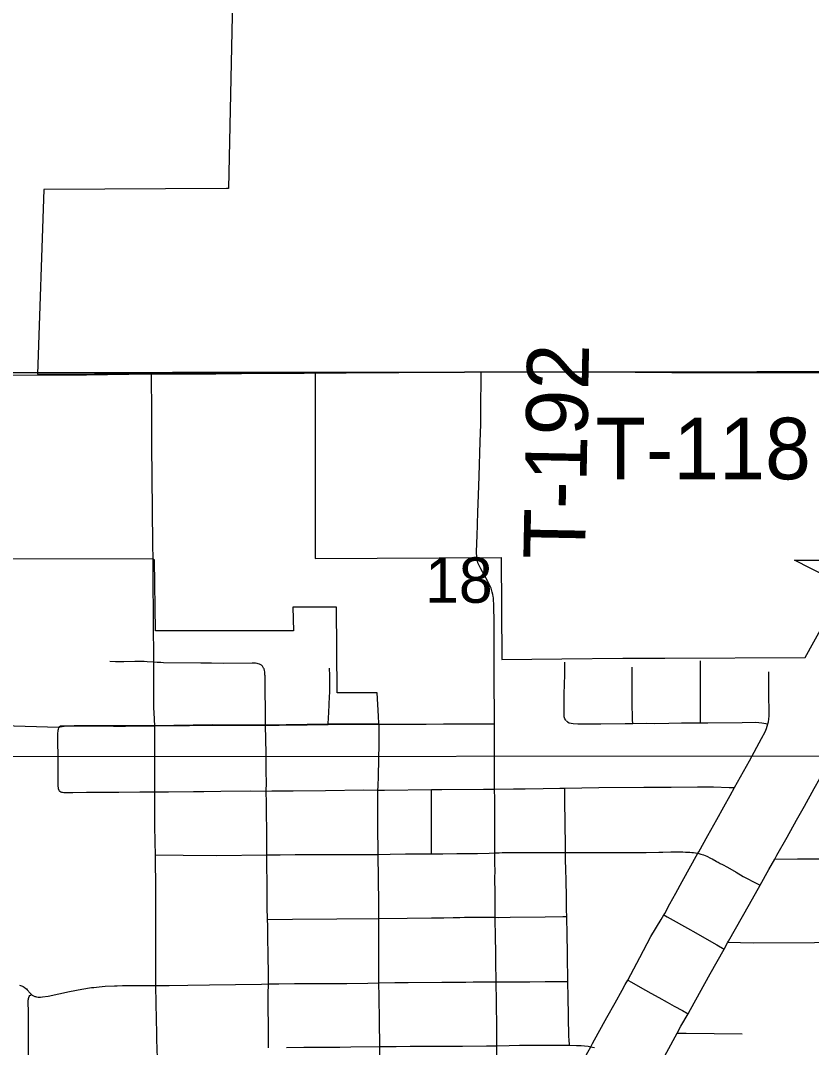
# Model space of a CAD drawing. Extents: x 0 to 34, y 0 to 22.
# Drawn here: x 3.7866 to 4.151, y 16.4424 to 16.9158 of the extents above; entities that cross this region are included whole.
import ezdxf

# ---------------------------------------------------------------- set-up
doc = ezdxf.new("R2010")
doc.units = 0
for name, color, linetype in [('GM_X_City_Street', 7, 'Continuous'), ('GM_X_Corporation', 7, 'Continuous'), ('GM_X_Section_Text', 7, 'Continuous'), ('GM_X_State_Route', 7, 'Continuous'), ('GM_X_Township_Road', 7, 'Continuous'), ('GM_X_Township_Road_Text', 7, 'Continuous')]:
    doc.layers.add(name, color=color, linetype=linetype)

msp = doc.modelspace()

# ---------------------------------------------------------------- linework, layer by layer
at = {"layer": 'GM_X_City_Street'}
for points in [[(4.038, 16.59303), (4.03779, 16.59328), (4.03744, 16.59383), (4.03724, 16.59435), (4.03712, 16.59485), (4.037, 16.59702), (4.03703, 16.60158), (4.03706, 16.60497), (4.03729, 16.61021), (4.03736, 16.61391), (4.03732, 16.61766), (4.03733, 16.61969), (4.03738, 16.62)], [(4.06864, 16.5918), (4.06861, 16.59346), (4.06848, 16.60165), (4.06848, 16.60596), (4.06846, 16.6081), (4.06846, 16.61364), (4.06843, 16.61585), (4.06841, 16.61775)], [(4.09996, 16.59198), (4.09994, 16.59339), (4.09987, 16.60153), (4.0999, 16.6157), (4.09982, 16.6206)], [(4.131, 16.59151), (4.13122, 16.59242), (4.13139, 16.59365), (4.13152, 16.59527), (4.13151, 16.59774), (4.13145, 16.60411), (4.13142, 16.61554)], [(3.80413, 16.56138), (3.80405, 16.56173), (3.80401, 16.56206), (3.80395, 16.5629), (3.80392, 16.56434), (3.80385, 16.56839), (3.80384, 16.57492), (3.80372, 16.58496), (3.80374, 16.58602), (3.80381, 16.58732), (3.8039, 16.58822), (3.80397, 16.58863), (3.80408, 16.58912), (3.80429, 16.58971)], [(3.80429, 16.58971), (3.80448, 16.58998), (3.80482, 16.59023), (3.80518, 16.59036), (3.80574, 16.59042), (3.80665, 16.59045), (3.81165, 16.5906), (3.82935, 16.59055), (3.83489, 16.59056), (3.84838, 16.59061), (3.8645, 16.59086), (3.87047, 16.59089), (3.87699, 16.59095), (3.89949, 16.59091), (3.90568, 16.59102), (3.90932, 16.59107), (3.91498, 16.59109), (3.91684, 16.5911), (3.91862, 16.59114), (3.92601, 16.59127), (3.9283, 16.5913), (3.93422, 16.59135), (3.9384, 16.59138), (3.94584, 16.59137), (3.94899, 16.59137), (3.95182, 16.59139), (3.95723, 16.59139), (3.96438, 16.59145), (3.97341, 16.59146), (3.9815, 16.59151), (3.98493, 16.59153), (3.98773, 16.59153), (3.99147, 16.59155), (3.99521, 16.59155), (3.99708, 16.59158), (3.99922, 16.59155), (4.00495, 16.59158)], [(3.85036, 16.38215), (3.85037, 16.39177), (3.85033, 16.39701), (3.85026, 16.40096), (3.8501, 16.40624), (3.84999, 16.41042), (3.84998, 16.41159), (3.84991, 16.41969), (3.84978, 16.43021), (3.84963, 16.43738), (3.84954, 16.44175), (3.84944, 16.44609), (3.8494, 16.44915), (3.84926, 16.45534), (3.84885, 16.47057), (3.84885, 16.4709), (3.84895, 16.48456), (3.84891, 16.49966), (3.84886, 16.51438), (3.84876, 16.53116), (3.84863, 16.53697), (3.84846, 16.54471), (3.84841, 16.56016), (3.84838, 16.59061)], [(3.90079, 16.44214), (3.90078, 16.45019), (3.90069, 16.46295), (3.90068, 16.46699), (3.90076, 16.47165), (3.90084, 16.47629), (3.90065, 16.48478), (3.90047, 16.49331), (3.90045, 16.49848), (3.90039, 16.50144), (3.90028, 16.50704), (3.90016, 16.51832), (3.90006, 16.52628), (3.90006, 16.53114), (3.90001, 16.5342), (3.89999, 16.53692), (3.89999, 16.53995), (3.9, 16.54297), (3.89997, 16.54979), (3.89991, 16.55504), (3.89983, 16.56059), (3.89985, 16.56434), (3.89979, 16.5696), (3.8998, 16.5748), (3.89979, 16.5762), (3.89975, 16.57791), (3.89949, 16.59091)], [(3.95268, 16.36983), (3.95253, 16.37994), (3.95253, 16.38316), (3.95244, 16.39867), (3.95247, 16.41276), (3.95233, 16.4269), (3.95219, 16.44276), (3.95199, 16.45469), (3.95183, 16.4657), (3.95173, 16.47212), (3.95169, 16.48195), (3.95172, 16.49246), (3.95174, 16.50179), (3.95168, 16.5089), (3.95138, 16.53135), (3.95128, 16.54472), (3.95118, 16.55571), (3.95124, 16.56098), (3.95129, 16.56271), (3.95145, 16.56757), (3.95176, 16.58245), (3.95182, 16.59139)], [(4.00605, 16.43401), (4.00601, 16.44308), (4.00601, 16.45111), (4.00591, 16.46342), (4.00575, 16.47271), (4.00564, 16.48189), (4.00556, 16.487), (4.00546, 16.49264), (4.00534, 16.50237), (4.00529, 16.50721), (4.00521, 16.51342), (4.0052, 16.52055), (4.00521, 16.52358), (4.00518, 16.5273), (4.00516, 16.52962), (4.00516, 16.53203), (4.00517, 16.53678), (4.00515, 16.54257), (4.00513, 16.55001), (4.0051, 16.55311), (4.00511, 16.55682), (4.00504, 16.5614), (4.00492, 16.58036), (4.00495, 16.59158)], [(4.038, 16.59303), (4.03829, 16.59278), (4.03865, 16.59254), (4.03943, 16.5921), (4.04031, 16.59182), (4.04122, 16.59167), (4.04339, 16.59162), (4.05394, 16.59161), (4.06512, 16.59178), (4.06864, 16.5918), (4.07505, 16.59182), (4.07877, 16.5918), (4.08528, 16.59191), (4.09117, 16.592), (4.09893, 16.59198), (4.09996, 16.59198), (4.10328, 16.59198), (4.1191, 16.59225), (4.12531, 16.59229), (4.12685, 16.59223), (4.12819, 16.59206), (4.131, 16.59151)], [(4.04657, 16.43781), (4.04934, 16.44272), (4.05014, 16.44414), (4.05277, 16.44895), (4.0568, 16.45623), (4.06054, 16.46293), (4.06383, 16.46886), (4.06522, 16.47134), (4.06638, 16.47344), (4.07197, 16.48392), (4.07698, 16.49346), (4.08183, 16.50143), (4.08301, 16.50351), (4.08339, 16.50418), (4.08573, 16.50855), (4.08853, 16.51352), (4.09149, 16.51887), (4.09872, 16.53189), (4.09909, 16.53256), (4.10324, 16.54005), (4.10739, 16.54741), (4.11068, 16.55333), (4.11356, 16.55859), (4.11557, 16.56218), (4.11833, 16.56711), (4.12243, 16.57447), (4.12808, 16.58477), (4.12969, 16.58781), (4.13033, 16.58938), (4.131, 16.59151)], [(3.80413, 16.56138), (3.80423, 16.56106), (3.80441, 16.56074), (3.80465, 16.56049), (3.80515, 16.56021), (3.80549, 16.5601), (3.80588, 16.56002), (3.80645, 16.55997), (3.81065, 16.55998), (3.81698, 16.56003), (3.8318, 16.56011), (3.84148, 16.56017), (3.84841, 16.56016), (3.85478, 16.56021), (3.86631, 16.56043), (3.87097, 16.56043), (3.87884, 16.56054), (3.89261, 16.56065), (3.89983, 16.56059), (3.90231, 16.56063), (3.9122, 16.56068), (3.92704, 16.56087), (3.94482, 16.56111), (3.95124, 16.56098), (3.95435, 16.56103), (3.97601, 16.56127), (3.98064, 16.56132), (3.99992, 16.5614), (4.00504, 16.5614)], [(3.97601, 16.53163), (3.97601, 16.53274), (3.97601, 16.55898), (3.97601, 16.56127)], [(4.00504, 16.5614), (4.01367, 16.5616), (4.01908, 16.56166), (4.02742, 16.56182), (4.03505, 16.56189), (4.03734, 16.56193), (4.05298, 16.56222), (4.07382, 16.56235), (4.08644, 16.56245), (4.09858, 16.56249), (4.10214, 16.56246), (4.10586, 16.56246), (4.1131, 16.56225), (4.11557, 16.56218)], [(4.03952, 16.44338), (4.03935, 16.44598), (4.03926, 16.44722), (4.03893, 16.46605), (4.03884, 16.47218), (4.03883, 16.47278), (4.03859, 16.4848), (4.03843, 16.49566), (4.03834, 16.50121), (4.0383, 16.50278), (4.03822, 16.5059), (4.03809, 16.51202), (4.03793, 16.51922), (4.0378, 16.52477), (4.03775, 16.52851), (4.03768, 16.53223), (4.03771, 16.53534), (4.03743, 16.556), (4.03738, 16.55974), (4.03734, 16.56193)], [(3.84876, 16.53116), (3.86154, 16.53107), (3.87689, 16.5309), (3.90006, 16.53114), (3.90617, 16.53125), (3.91308, 16.53134), (3.9185, 16.53136), (3.92953, 16.5314), (3.94207, 16.5313), (3.95138, 16.53135), (3.95684, 16.53151), (3.9639, 16.53159), (3.97567, 16.53163), (3.97601, 16.53163), (3.98118, 16.53166), (3.98764, 16.53174), (3.99238, 16.53181), (3.99715, 16.53187), (4.00258, 16.53201), (4.00516, 16.53203), (4.0071, 16.53216), (4.00855, 16.53223), (4.00939, 16.53225), (4.01127, 16.53227), (4.01344, 16.53233), (4.01673, 16.53233), (4.02399, 16.53227), (4.0271, 16.53225), (4.02833, 16.53225), (4.02987, 16.53224), (4.03111, 16.53223), (4.03265, 16.53222), (4.03388, 16.5322), (4.03768, 16.53223), (4.04112, 16.53225), (4.05362, 16.53226), (4.06002, 16.53226), (4.06905, 16.53227), (4.07479, 16.53229), (4.08067, 16.53242), (4.08253, 16.53246), (4.08622, 16.53251), (4.08776, 16.53253), (4.08868, 16.53254), (4.09021, 16.53252), (4.09174, 16.53251), (4.09294, 16.53247), (4.0941, 16.53243), (4.09496, 16.53237), (4.09583, 16.53231), (4.09674, 16.53223), (4.09765, 16.53209), (4.09872, 16.53189), (4.1001, 16.53153), (4.10131, 16.53112), (4.10277, 16.53051), (4.10444, 16.52968), (4.10526, 16.52927), (4.10708, 16.52827), (4.10755, 16.528), (4.10798, 16.52776), (4.10898, 16.52723), (4.10999, 16.52673), (4.11231, 16.52548), (4.11629, 16.52312), (4.11949, 16.52127), (4.12612, 16.51783), (4.12736, 16.51719)], [(4.13414, 16.52926), (4.1446, 16.52931), (4.15577, 16.5294)], [(4.08301, 16.50351), (4.08461, 16.50257), (4.08595, 16.50177), (4.09386, 16.49734), (4.09767, 16.4952), (4.10502, 16.49102), (4.1074, 16.48966), (4.11077, 16.48775)], [(3.90039, 16.50144), (3.91185, 16.50151), (3.93231, 16.50167), (3.95174, 16.50179), (3.96479, 16.50195), (3.97594, 16.50208), (3.98159, 16.5022), (3.98591, 16.50231), (3.989, 16.50236), (3.99116, 16.50238), (3.99302, 16.50239), (3.99455, 16.50239), (3.99639, 16.5024), (3.99972, 16.50237), (4.00534, 16.50237), (4.00693, 16.50236), (4.01212, 16.5024), (4.02837, 16.50263), (4.0364, 16.50275), (4.0383, 16.50278)], [(4.11255, 16.49088), (4.12422, 16.49068), (4.15248, 16.49082), (4.1798, 16.4909), (4.1968, 16.49115)], [(3.78611, 16.47104), (3.78662, 16.47092), (3.7874, 16.47063), (3.78783, 16.47042), (3.78822, 16.47017), (3.78862, 16.46988), (3.78927, 16.46934), (3.7896, 16.46899), (3.79095, 16.46739), (3.79156, 16.46683), (3.79199, 16.4665), (3.79256, 16.46618), (3.79315, 16.46592), (3.79344, 16.46581), (3.7939, 16.4657), (3.79475, 16.46556), (3.7951, 16.46557), (3.79574, 16.46558), (3.79664, 16.46566), (3.79924, 16.46608), (3.8091, 16.46812), (3.8148, 16.46927), (3.81924, 16.46995), (3.82034, 16.47009), (3.82279, 16.47036), (3.82557, 16.4706), (3.8299, 16.47076), (3.83113, 16.4708), (3.8336, 16.47088), (3.84385, 16.4709), (3.84885, 16.4709), (3.85503, 16.4709), (3.86373, 16.47103), (3.87365, 16.47121), (3.89754, 16.4716), (3.90076, 16.47165), (3.9056, 16.47173), (3.91276, 16.47184), (3.92177, 16.47179), (3.92984, 16.47179), (3.93697, 16.47188), (3.94653, 16.47209), (3.95173, 16.47212), (3.959, 16.47232), (3.96522, 16.47237), (3.98068, 16.47242), (3.98221, 16.47244), (3.99174, 16.47255), (3.99513, 16.47261), (4.00066, 16.47268), (4.00431, 16.47271), (4.00575, 16.47271), (4.01225, 16.47269), (4.02119, 16.47271), (4.02829, 16.4728), (4.03635, 16.47278), (4.03883, 16.47278)], [(4.06638, 16.47344), (4.06803, 16.47253), (4.07215, 16.47019), (4.077, 16.46742), (4.08062, 16.46541), (4.08449, 16.46327), (4.0878, 16.46145), (4.0916, 16.45936), (4.09419, 16.45794)], [(3.79058, 16.41141), (3.79047, 16.42527), (3.79031, 16.43818), (3.79026, 16.44142), (3.79023, 16.44294), (3.79022, 16.45023), (3.79018, 16.45878), (3.79016, 16.46332), (3.79015, 16.4642), (3.79018, 16.46463), (3.79023, 16.46497), (3.79033, 16.46536), (3.79054, 16.46586), (3.79082, 16.46627), (3.79112, 16.46653), (3.79156, 16.46683)], [(4.08909, 16.44896), (4.09329, 16.44891), (4.11906, 16.44863)], [(3.90908, 16.44233), (3.91714, 16.44244), (3.92571, 16.44256), (3.93376, 16.44259), (3.93884, 16.44262), (3.95219, 16.44276), (3.95968, 16.44288), (3.96612, 16.44294), (3.97966, 16.44303), (3.99021, 16.44303), (4.0013, 16.44309), (4.00601, 16.44308), (4.01173, 16.4433), (4.01646, 16.44339), (4.02234, 16.44343), (4.03145, 16.44337), (4.03472, 16.44337), (4.03792, 16.4434), (4.03952, 16.44338), (4.04278, 16.44334), (4.04493, 16.44325), (4.04648, 16.44315), (4.0482, 16.44294), (4.04934, 16.44272), (4.05015, 16.44257), (4.05106, 16.44234)]]:
    msp.add_lwpolyline(points, dxfattribs=at)
at = {"layer": 'GM_X_Corporation'}
for points in [[(3.73479, 17.25336), (4.27027, 17.25592), (4.26039, 16.75407), (3.72171, 16.75343)], [(4.26039, 16.75407), (4.25771, 16.57674), (3.71695, 16.57631), (3.72171, 16.75343)]]:
    msp.add_lwpolyline(points, close=True, dxfattribs=at)
for points in [[(3.88601, 17.00509), (3.88242, 16.83841), (3.88148, 16.83841), (3.79728, 16.83784), (3.79445, 16.75271), (3.8468, 16.75313), (3.92233, 16.75361), (3.92233, 16.66781), (4.00807, 16.66821), (4.00832, 16.62116), (4.03597, 16.62152), (4.06414, 16.62187), (4.08342, 16.62191), (4.14813, 16.62214), (4.16643, 16.65514), (4.14327, 16.6671), (4.1618, 16.66707)], [(3.71658, 16.59262), (3.80418, 16.58998), (3.80451, 16.59039), (3.80506, 16.59063), (3.80654, 16.59072), (3.81126, 16.59086), (3.84827, 16.59088), (3.87498, 16.59121), (3.89938, 16.59118), (3.92819, 16.59157), (3.95171, 16.59167), (3.95148, 16.59518), (3.95096, 16.60579), (3.93253, 16.60581), (3.93219, 16.64542), (3.91208, 16.64543), (3.91235, 16.63445), (3.84882, 16.63451), (3.84832, 16.66701), (3.84752, 16.66766), (3.7183, 16.66747)]]:
    msp.add_lwpolyline(points, dxfattribs=at)
at = {"layer": 'GM_X_State_Route'}
msp.add_lwpolyline([(4.08055, 16.43308), (4.08909, 16.44896), (4.09083, 16.4522), (4.09419, 16.45794), (4.09536, 16.45993), (4.10431, 16.47638), (4.11077, 16.48775), (4.11255, 16.49088), (4.11282, 16.49135), (4.12247, 16.50851), (4.12736, 16.51719), (4.13145, 16.52446), (4.13414, 16.52926), (4.13512, 16.53102), (4.13977, 16.53933), (4.14417, 16.54721), (4.14776, 16.55364), (4.15235, 16.56175), (4.15749, 16.57098)], dxfattribs=at)
at = {"layer": 'GM_X_Township_Road'}
for points in [[(3.72053, 16.75191), (3.73478, 16.75227), (3.75595, 16.75225), (3.77273, 16.75232), (3.78236, 16.75236), (3.79456, 16.75244)], [(3.79456, 16.75244), (3.81697, 16.75252), (3.83655, 16.75274), (3.84691, 16.75285)], [(3.84691, 16.75285), (3.85084, 16.75289), (3.87664, 16.75299), (3.90026, 16.75322), (3.90506, 16.75323), (3.90555, 16.75324)], [(3.84763, 16.66739), (3.84753, 16.67439), (3.84742, 16.69027), (3.84714, 16.72), (3.84707, 16.73723), (3.84694, 16.75014), (3.84691, 16.75285)], [(3.90555, 16.75324), (3.91733, 16.75329), (3.9224, 16.75333)], [(3.9224, 16.75333), (3.9366, 16.75346), (3.94654, 16.75348), (3.96083, 16.75358), (3.97885, 16.75371), (3.99889, 16.75382)], [(3.99683, 16.66795), (3.99677, 16.66864), (3.9967, 16.67038), (3.99679, 16.67521), (3.99693, 16.67808), (3.99735, 16.68914), (3.99767, 16.69701), (3.9979, 16.70571), (3.9984, 16.72177), (3.99867, 16.72949), (3.99864, 16.73508), (3.99889, 16.75382)], [(3.99889, 16.75382), (4.00341, 16.75384), (4.02764, 16.75384), (4.05282, 16.75378), (4.08669, 16.75357), (4.1159, 16.75354), (4.15319, 16.75348), (4.19204, 16.75342), (4.2113, 16.75333), (4.2343, 16.75331), (4.24331, 16.75333), (4.24829, 16.75331), (4.25596, 16.75352)], [(3.84787, 16.63421), (3.84785, 16.64195), (3.84779, 16.64652), (3.84771, 16.65211), (3.84768, 16.65763), (3.84763, 16.66739)], [(4.00495, 16.59158), (4.00475, 16.61447), (4.00477, 16.62145), (4.00479, 16.62881), (4.00478, 16.63963), (4.00469, 16.6448), (4.00462, 16.64727), (4.00458, 16.6481), (4.00452, 16.64897), (4.00446, 16.64959), (4.00434, 16.65033), (4.00418, 16.65119), (4.00393, 16.65224), (4.00341, 16.65407), (4.00305, 16.65501), (4.00242, 16.65627), (4.00172, 16.65757), (3.99865, 16.66299), (3.99736, 16.66576), (3.99707, 16.6666), (3.99694, 16.66714), (3.99683, 16.66795)], [(3.84801, 16.62017), (3.84795, 16.62523), (3.84787, 16.63421)], [(3.82773, 16.62041), (3.83031, 16.62036), (3.8341, 16.62036), (3.83917, 16.62039), (3.84355, 16.62039), (3.84492, 16.62034), (3.84801, 16.62017)], [(3.84838, 16.59061), (3.84812, 16.59658), (3.84805, 16.59898), (3.84805, 16.60099), (3.84803, 16.61196), (3.84801, 16.62017)], [(3.84801, 16.62017), (3.84959, 16.62005), (3.85032, 16.62), (3.85115, 16.61996), (3.85241, 16.61992), (3.86966, 16.6197), (3.87453, 16.61963)], [(3.87453, 16.61963), (3.87988, 16.61955), (3.89328, 16.61967), (3.8948, 16.61962), (3.89551, 16.61953), (3.89591, 16.61944), (3.89652, 16.61924), (3.89718, 16.61892), (3.89744, 16.61873)], [(3.89949, 16.59091), (3.8994, 16.59941), (3.8993, 16.60544), (3.89928, 16.60902), (3.89925, 16.61203), (3.89923, 16.61372), (3.89921, 16.61413), (3.89919, 16.61468), (3.89917, 16.61507), (3.89912, 16.61561), (3.89902, 16.61622), (3.89878, 16.6169), (3.89858, 16.61731), (3.89842, 16.6176), (3.89825, 16.61786), (3.898, 16.61818), (3.89744, 16.61873)], [(3.9283, 16.5913), (3.92837, 16.59189), (3.92854, 16.59403), (3.92886, 16.60015), (3.92899, 16.60455), (3.92902, 16.60564), (3.92905, 16.60698), (3.92908, 16.60997), (3.92903, 16.61378), (3.92899, 16.61722)]]:
    msp.add_lwpolyline(points, dxfattribs=at)

# ---------------------------------------------------------------- texts
at = {"layer": 'GM_X_Section_Text'}
msp.add_text('18', height=0.020928, rotation=0, dxfattribs=at).set_placement((3.97298, 16.64738))
at = {"layer": 'GM_X_Township_Road_Text'}
for s, rotation, p in [('T-192', 88.8884, (4.04666, 16.66725)), ('T-118', 0, (4.05152, 16.70429))]:
    msp.add_text(s, height=0.028409, rotation=rotation, dxfattribs=at).set_placement(p)

doc.saveas('drawing.dxf')
